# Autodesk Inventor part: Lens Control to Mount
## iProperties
Created: 2006-10
Part Number: Lens Control to Mount
Document SubType Name: Modeling
Designer: Lab User
Author: Lab User
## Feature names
1. Extrusion1
2. Hole1
3. Hole2
